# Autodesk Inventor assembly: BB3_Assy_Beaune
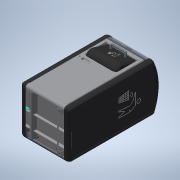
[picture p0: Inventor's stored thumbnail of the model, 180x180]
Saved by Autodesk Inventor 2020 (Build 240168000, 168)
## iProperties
Created: 2008-11
Part Number: BB3_Assy_Beaune
Document SubType Name: Assembly
Designer: claivier
Author: claivier
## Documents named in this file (12)
- D:\Cours\1-Cours-2020-21\1-Site\Elèves\TSTI2D\Tronc-commun\EDC-RDM-Big-Belly\lib\Big-Belly\Big-Belly\BB3_Assy_Beaune.iam
- D:\Cours\1-Cours-2020-21\1-Site\Elèves\TSTI2D\Tronc-commun\EDC-RDM-Big-Belly\lib\Big-Belly\Big-Belly\BB3_Chassis.iam
- D:\Cours\1-Cours-2020-21\1-Site\Elèves\TSTI2D\Tronc-commun\EDC-RDM-Big-Belly\lib\Big-Belly\Big-Belly\BB3_Axe_Moteur.iam
- D:\Cours\1-Cours-2020-21\1-Site\Elèves\TSTI2D\Tronc-commun\EDC-RDM-Big-Belly\lib\Big-Belly\Big-Belly\BB3_Pignon_Bas.iam
- D:\Cours\1-Cours-2020-21\1-Site\Elèves\TSTI2D\Tronc-commun\EDC-RDM-Big-Belly\lib\Big-Belly\Big-Belly\BB3_Coulissant_Vertical.iam
- D:\Cours\1-Cours-2020-21\1-Site\Elèves\TSTI2D\Tronc-commun\EDC-RDM-Big-Belly\lib\Big-Belly\Big-Belly\BB3_Porte.iam
- D:\Cours\1-Cours-2020-21\1-Site\Elèves\TSTI2D\Tronc-commun\EDC-RDM-Big-Belly\lib\Big-Belly\Big-Belly\BB3_Dévidoir.iam
- D:\Cours\1-Cours-2020-21\1-Site\Elèves\TSTI2D\Tronc-commun\EDC-RDM-Big-Belly\lib\Big-Belly\Big-Belly\BB3_Protection_Avant.iam
- D:\Cours\1-Cours-2020-21\1-Site\Elèves\TSTI2D\Tronc-commun\EDC-RDM-Big-Belly\lib\Big-Belly\Big-Belly\BB3_Panneau_Solaire.iam
- D:\Cours\1-Cours-2020-21\1-Site\Elèves\TSTI2D\Tronc-commun\EDC-RDM-Big-Belly\lib\Big-Belly\Big-Belly\BB3_Rame_Compacteur_2.iam
- D:\Cours\1-Cours-2020-21\1-Site\Elèves\TSTI2D\Tronc-commun\EDC-RDM-Big-Belly\lib\Big-Belly\Big-Belly\BB3_Coulissant_Vertical_Crémaillère.ipt
- D:\Cours\1-Cours-2020-21\1-Site\Elèves\TSTI2D\Tronc-commun\EDC-RDM-Big-Belly\lib\Big-Belly\Big-Belly\chaine.ipt
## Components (16 placed, 11 different names)
1. BB3_Chassis:1 [sub-assembly] — Affleurement:1, Plaquage:2, Affleurement:3, Affleurement:4, Plaquage:6, Affleurement:8, Affleurement:9, Plaquage:9, Plaquage:8, Angle:3, Plaquage:11, Plaquage:12, Angle:5, Affleurement:10, Plaquage:13, Plaquage:14, Angle:6, Plaquage:3, Plaquage:1
2. BB3_Axe_Moteur:1 [sub-assembly] — Affleurement:1, Angle:1, Angle:2, Rotation/Translation:1, Affleurement:6, Affleurement:2, Affleurement:11, Tangente:1, Affleurement:13, Tangente:3, Plaquage:1, Placage:20, Placage:22
3. BB3_Pignon_Bas:1 [sub-assembly] — Plaquage:2, Angle:1, Affleurement:2, Affleurement:14, Tangente:4, Placage:21, Affleurement:15
4. BB3_Rame_Compacteur_2:1 [sub-assembly] — Affleurement:3, Affleurement:4, Plaquage:4, Plaquage:5, Rotation/Translation:1, Plaquage:3, Plaquage:10, Plaquage:16, Plaquage:17, Plaquage:19, Plaquage:18
5. BB3_Coulissant_Vertical:1 [sub-assembly] — Plaquage:4, Plaquage:5, Plaquage:10
6. BB3_Pignon_Bas:2 [sub-assembly] — Plaquage:6, Angle:2, Affleurement:6, Affleurement:12, Tangente:2, Placage:23, Affleurement:16
7. BB3_Porte:1 [sub-assembly] — Plaquage:9, Plaquage:8, Affleurement:7, Plaquage:7, Angle:4, Angle:3, Angle:7
8. BB3_Dévidoir:1 [sub-assembly] — Affleurement:7, Plaquage:7, Angle:4, Angle:7
9. BB3_Protection_Avant:1 [sub-assembly] — Plaquage:11, Plaquage:12, Angle:5
10. BB3_Panneau_Solaire:1 [sub-assembly] — Plaquage:13, Plaquage:14, Angle:6
11. BB3_Coulissant_Vertical_Crémaillère:1 — Plaquage:16, Affleurement:11, Tangente:1
12. BB3_Coulissant_Vertical_Crémaillère:2 — Plaquage:17, Affleurement:12, Tangente:2
13. BB3_Coulissant_Vertical_Crémaillère:3 — Affleurement:13, Tangente:3, Plaquage:18
14. BB3_Coulissant_Vertical_Crémaillère:4 — Affleurement:14, Tangente:4, Plaquage:19
15. chaine:1 — Placage:20, Placage:21, Affleurement:15
16. chaine:2 — Placage:22, Placage:23, Affleurement:16
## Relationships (49: Mate 22, Flush 15, Angle 7, Tangent 4, RelateRotateTranslate 1)
- Affleurement:1 [Flush]: BB3_Chassis:1 ↔ BB3_Axe_Moteur:1
- Plaquage:2 [Mate]: BB3_Chassis:1 ↔ BB3_Pignon_Bas:1
- Affleurement:3 [Flush]: BB3_Chassis:1 ↔ BB3_Rame_Compacteur_2:1
- Affleurement:4 [Flush]: BB3_Chassis:1 ↔ BB3_Rame_Compacteur_2:1
- Angle:1: BB3_Axe_Moteur:1 ↔ BB3_Pignon_Bas:1
- Plaquage:4 [Mate]: BB3_Rame_Compacteur_2:1 ↔ BB3_Coulissant_Vertical:1
- Plaquage:5 [Mate]: BB3_Rame_Compacteur_2:1 ↔ BB3_Coulissant_Vertical:1
- Plaquage:6 [Mate]: BB3_Chassis:1 ↔ BB3_Pignon_Bas:2
- Angle:2: BB3_Axe_Moteur:1 ↔ BB3_Pignon_Bas:2
- Rotation/Translation:1 [RelateRotateTranslate]: BB3_Axe_Moteur:1 ↔ BB3_Rame_Compacteur_2:1
- Affleurement:8 [Flush]: BB3_Chassis:1
- Affleurement:9 [Flush]: BB3_Chassis:1
- Plaquage:9 [Mate]: BB3_Chassis:1 ↔ BB3_Porte:1
- Plaquage:8 [Mate]: BB3_Chassis:1 ↔ BB3_Porte:1
- Affleurement:7 [Flush]: BB3_Porte:1 ↔ BB3_Dévidoir:1
- Plaquage:7 [Mate]: BB3_Porte:1 ↔ BB3_Dévidoir:1
- Angle:4: BB3_Porte:1 ↔ BB3_Dévidoir:1
- Angle:3: BB3_Chassis:1 ↔ BB3_Porte:1
- Plaquage:11 [Mate]: BB3_Chassis:1 ↔ BB3_Protection_Avant:1
- Plaquage:12 [Mate]: BB3_Chassis:1 ↔ BB3_Protection_Avant:1
- Angle:5: BB3_Chassis:1 ↔ BB3_Protection_Avant:1
- Affleurement:10 [Flush]: BB3_Chassis:1
- Plaquage:13 [Mate]: BB3_Chassis:1 ↔ BB3_Panneau_Solaire:1
- Plaquage:14 [Mate]: BB3_Chassis:1 ↔ BB3_Panneau_Solaire:1
- Angle:6: BB3_Chassis:1 ↔ BB3_Panneau_Solaire:1
- Plaquage:3 [Mate]: BB3_Chassis:1 ↔ BB3_Rame_Compacteur_2:1
- Affleurement:6 [Flush]: BB3_Axe_Moteur:1 ↔ BB3_Pignon_Bas:2
- Affleurement:2 [Flush]: BB3_Axe_Moteur:1 ↔ BB3_Pignon_Bas:1
- Plaquage:10 [Mate]: BB3_Rame_Compacteur_2:1 ↔ BB3_Coulissant_Vertical:1
- Angle:7: BB3_Porte:1 ↔ BB3_Dévidoir:1
- Plaquage:16 [Mate]: BB3_Rame_Compacteur_2:1 ↔ BB3_Coulissant_Vertical_Crémaillère:1
- Affleurement:11 [Flush]: BB3_Axe_Moteur:1 ↔ BB3_Coulissant_Vertical_Crémaillère:1
- Tangente:1: BB3_Axe_Moteur:1 ↔ BB3_Coulissant_Vertical_Crémaillère:1
- Plaquage:17 [Mate]: BB3_Rame_Compacteur_2:1 ↔ BB3_Coulissant_Vertical_Crémaillère:2
- Affleurement:12 [Flush]: BB3_Pignon_Bas:2 ↔ BB3_Coulissant_Vertical_Crémaillère:2
- Tangente:2: BB3_Pignon_Bas:2 ↔ BB3_Coulissant_Vertical_Crémaillère:2
- Affleurement:13 [Flush]: BB3_Axe_Moteur:1 ↔ BB3_Coulissant_Vertical_Crémaillère:3
- Tangente:3: BB3_Axe_Moteur:1 ↔ BB3_Coulissant_Vertical_Crémaillère:3
- Affleurement:14 [Flush]: BB3_Pignon_Bas:1 ↔ BB3_Coulissant_Vertical_Crémaillère:4
- Tangente:4: BB3_Pignon_Bas:1 ↔ BB3_Coulissant_Vertical_Crémaillère:4
- Plaquage:19 [Mate]: BB3_Rame_Compacteur_2:1 ↔ BB3_Coulissant_Vertical_Crémaillère:4
- Plaquage:18 [Mate]: BB3_Rame_Compacteur_2:1 ↔ BB3_Coulissant_Vertical_Crémaillère:3
- Plaquage:1 [Mate]: BB3_Chassis:1 ↔ BB3_Axe_Moteur:1
- Placage:20 [Mate]: BB3_Axe_Moteur:1 ↔ chaine:1
- Placage:21 [Mate]: BB3_Pignon_Bas:1 ↔ chaine:1
- Affleurement:15 [Flush]: BB3_Pignon_Bas:1 ↔ chaine:1
- Placage:22 [Mate]: BB3_Axe_Moteur:1 ↔ chaine:2
- Placage:23 [Mate]: BB3_Pignon_Bas:2 ↔ chaine:2
- Affleurement:16 [Flush]: BB3_Pignon_Bas:2 ↔ chaine:2
